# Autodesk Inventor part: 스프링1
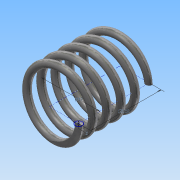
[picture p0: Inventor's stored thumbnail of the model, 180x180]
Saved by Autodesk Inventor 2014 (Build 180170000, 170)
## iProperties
Created: 2016-01
Part Number: 스프링1
Material: 강철, 탄소
Document SubType Name: Modeling
Designer: Administrator
Mass: 6.46669 g
Surface Area: 16.7182 cm^2
Volume: 0.821689 cm^3
Density: 7.87 g/cm^3
Appearance: 반연마
Author: Administrator
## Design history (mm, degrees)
sketch "스케치1"
  geometry: L1 (0, 0)-(8.5, 0); L2 (8.5, 0)-(8.5, 20.5); L3 (8.5, 20.5)-(0, 20.5); L4 (0, 20.5)-(0, 0); C1 r 1 at (8.5, 0)
  constraints: 8 end point, 2 parallel, 1 centre point, 1 coincident, 1 horizontal, 1 perpendicular
  dimensions: "d0" = 20.5 distance of L1.end L2.end (derived); "d1" = 2 diameter of C1; "d2" = 17 diameter of L2 L4
feature "코일1" sketch "스케치1" pitch "d3" = 10; turns "d5" = 5; dims "d4" = 20.5 (= d0), "d6" = 0, angle "d7" = 90 deg, angle "d8" = 90 deg, "d9" = 0, "d10" = 0
sketch "스케치2"
  geometry: L1 (-9.5, 0)-(-7.5, 0) reference; 1 further point
  constraints: 1 horizontal alignment
extrude "돌출1" cut sketch "스케치2" distance "d11" = 10; taper "d12" = 0 deg
node "작업 평면1"
sketch "스케치3"
  geometry: L1 (-7.5, 0)-(-9.5, 0) reference; 1 further point
  constraints: 1 horizontal alignment
extrude "돌출2" cut sketch "스케치3" stored distance "d14" = 10; taper "d15" = 0 deg
node "솔리드1"
node "절단 모서리 투영1"
node "절단 모서리 투영2"
other parameters: "d13" = 20.5 (= d0)
